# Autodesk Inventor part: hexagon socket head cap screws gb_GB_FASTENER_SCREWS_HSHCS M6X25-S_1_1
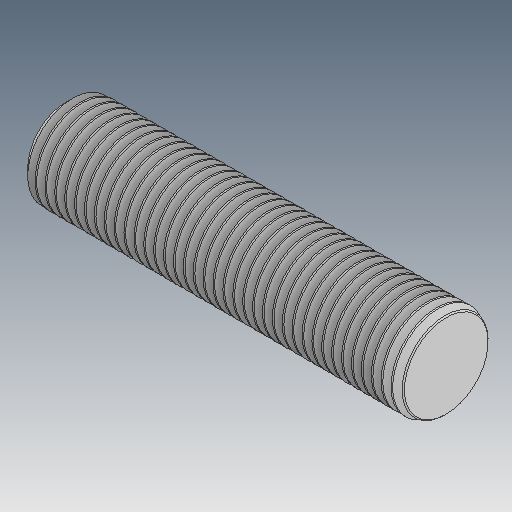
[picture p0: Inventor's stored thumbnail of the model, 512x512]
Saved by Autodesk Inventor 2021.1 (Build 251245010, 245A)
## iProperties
Created: 2019-04
Part Number: hexagon socket head cap screws gb_GB_FASTENER_SCREWS_HSHCS M6X25-S_1_1
Material: Ogólny
Document SubType Name: Modeling
Designer: user
Density: 1 g/cm^3
Appearance: Domyślna
Author: user
Revision Number: ÈÎºÎ
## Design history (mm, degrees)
feature "ÊäÈë1"
node "Bryła1"
